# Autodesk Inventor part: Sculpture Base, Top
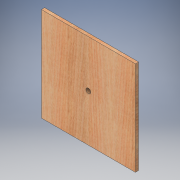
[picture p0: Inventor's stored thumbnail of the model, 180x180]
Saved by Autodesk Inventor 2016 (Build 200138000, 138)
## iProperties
Created: 2015-08
Part Number: Sculpture Base, Top
Material: Wood (Birch)
Document SubType Name: Modeling
Designer: Chris Eckert
Density: 0.55 g/cm^3
Appearance: Birch - Natural Polished
Author: Chris Eckert
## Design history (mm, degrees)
sketch "Sketch1"
  geometry: L1 (-185.738, 185.738)-(185.737, 185.738); L2 (185.737, 185.738)-(185.737, -185.737); L3 (185.737, -185.737)-(-185.737, -185.738); L4 (-185.737, -185.738)-(-185.738, 185.738); 1 further point
  constraints: 8 end point, 2 parallel, 1 horizontal, 1 perpendicular
  dimensions: "d0" = 371.475 distance of L1.start L1.end (= OverallWidth + 2 x DatoOverhang); "d1" = 371.475 distance of L3.end L1.start (= OverallDepth + 2 x DatoOverhang); "d2" = 185.7375 distance from line of L4 point (0, 0) (= 0.5 x d0); "d3" = 185.7375 distance from line of point (0, 0) L1 (= 0.5 x d1)
extrude "Extrusion1" new body sketch "Sketch1" distance "d4" = 12.7 (= WoodThickness); taper "d5" = 0 deg
sketch "Sketch2"
  geometry: 2 further points
  constraints: 1 coincident
hole "Hole1" sketch "Sketch2" at (0, 0) diameter "d6" = 19.05; stored, may be unused: countersink angle "d10" = 82 deg, drill point angle "d12" = 118 deg; dims "d7" = 19.05, "d8" = 9.525, "d9" = 6.35, "d11" = 25.4
body "Solid1"
other parameters: "WoodThickness" = 12.7 [user parameter; used in 1 equation term], "OverallWidth" = 368.3 [user parameter; used in 1 equation term], "OverallDepth" = 368.3 [user parameter; used in 1 equation term], "DatoOverhang" = 1.5875 [user parameter; used in 2 equation terms], "OverallHeight" = 1193.8 [user parameter]
